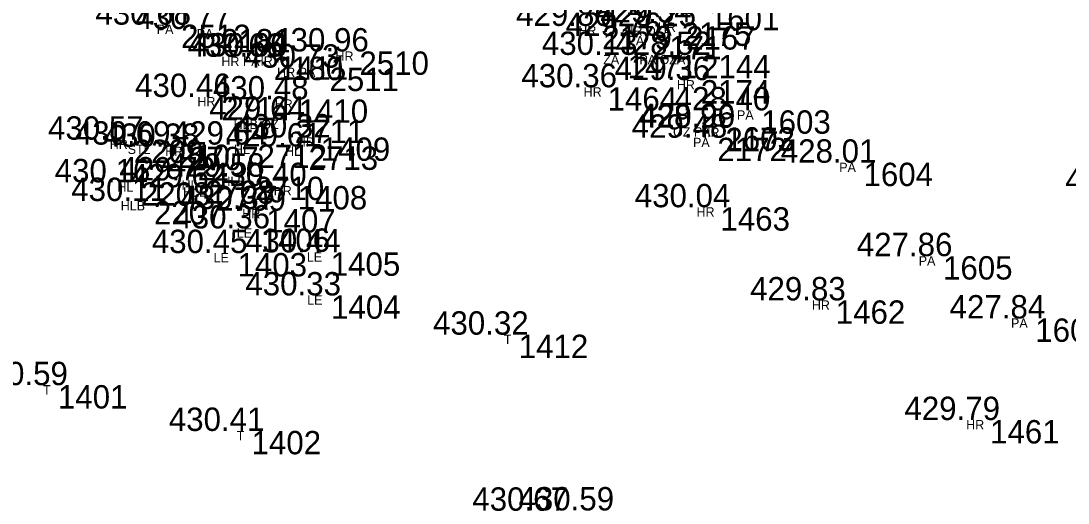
# Model space of a CAD drawing. Extents: x -639390 to -639075, y -1138747 to -1138358.
# Drawn here: x -639296.34 to -639262.75, y -1138603.62 to -1138588.15 of the extents above; entities that cross this region are included whole.
import ezdxf

# ---------------------------------------------------------------- set-up
doc = ezdxf.new("R2010")
doc.units = 0
for name, color, linetype in [('Vrstva 11', 7, 'Continuous'), ('Vrstva 12', 7, 'Continuous'), ('Vrstva 13', 7, 'Continuous'), ('Vrstva 57', 7, 'Continuous')]:
    doc.layers.add(name, color=color, linetype=linetype)

msp = doc.modelspace()

# ---------------------------------------------------------------- linework, layer by layer
at = {"layer": 'Vrstva 11'}
for p, q in [((-639275.42, -1138588.2), (-639275.42, -1138588.2)), ((-639291.48, -1138588.27), (-639291.48, -1138588.27)), ((-639290.2, -1138588.41), (-639290.2, -1138588.41)), ((-639277.97, -1138588.31), (-639277.97, -1138588.31)), ((-639275.28, -1138588.32), (-639275.28, -1138588.32)), ((-639276.38, -1138588.63), (-639276.38, -1138588.63)), ((-639285.76, -1138589.13), (-639285.76, -1138589.13)), ((-639277.16, -1138589.24), (-639277.16, -1138589.24)), ((-639274.8, -1138589.24), (-639274.8, -1138589.24)), ((-639288.51, -1138589.3), (-639288.51, -1138589.3)), ((-639288.35, -1138589.29), (-639288.35, -1138589.29)), ((-639286.72, -1138589.65), (-639286.72, -1138589.65)), ((-639277.8, -1138590.28), (-639277.8, -1138590.28)), ((-639274.81, -1138590.05), (-639274.81, -1138590.05)), ((-639290.19, -1138590.59), (-639290.19, -1138590.59)), ((-639287.71, -1138590.67), (-639287.71, -1138590.67)), ((-639272.87, -1138591.02), (-639272.87, -1138591.02)), ((-639287.83, -1138591.32), (-639287.83, -1138591.32)), ((-639274.02, -1138591.56), (-639274.02, -1138591.56)), ((-639274.02, -1138591.58), (-639274.02, -1138591.58)), ((-639293, -1138591.96), (-639293, -1138591.96)), ((-639287, -1138591.89), (-639287, -1138591.89)), ((-639274.28, -1138591.9), (-639274.28, -1138591.9)), ((-639292.14, -1138592.12), (-639292.14, -1138592.12)), ((-639291.22, -1138592.19), (-639291.22, -1138592.19)), ((-639289.03, -1138592.12), (-639289.03, -1138592.12)), ((-639287.39, -1138592.18), (-639287.39, -1138592.18)), ((-639269.59, -1138592.7), (-639269.59, -1138592.7)), ((-639290.71, -1138593.27), (-639290.71, -1138593.27)), ((-639289.12, -1138593.15), (-639289.12, -1138593.15)), ((-639292.77, -1138593.33), (-639292.77, -1138593.33)), ((-639290.35, -1138593.49), (-639290.35, -1138593.49)), ((-639287.74, -1138593.45), (-639287.74, -1138593.45)), ((-639292.35, -1138593.93), (-639292.35, -1138593.93)), ((-639288.75, -1138594.19), (-639288.75, -1138594.19)), ((-639274.18, -1138594.13), (-639274.18, -1138594.13)), ((-639288.93, -1138594.81), (-639288.93, -1138594.81)), ((-639289.67, -1138595.6), (-639289.67, -1138595.6)), ((-639286.68, -1138595.58), (-639286.68, -1138595.58)), ((-639267.04, -1138595.7), (-639267.04, -1138595.7)), ((-639286.67, -1138596.96), (-639286.67, -1138596.96)), ((-639270.48, -1138597.12), (-639270.48, -1138597.12)), ((-639264.08, -1138597.7), (-639264.08, -1138597.7)), ((-639280.65, -1138598.22), (-639280.65, -1138598.22)), ((-639295.43, -1138599.84), (-639295.43, -1138599.84)), ((-639265.53, -1138600.96), (-639265.53, -1138600.96)), ((-639289.22, -1138601.31), (-639289.22, -1138601.31))]:
    msp.add_line(p, q, dxfattribs=at)

# ---------------------------------------------------------------- texts
at = {"layer": 'Vrstva 12'}
for s, p in [('430.68 ', (-639293.949, -1138588.27)), ('429.86 ', (-639280.456, -1138588.31)), ('429.34 ', (-639277.889, -1138588.2)), ('429.25 ', (-639277.75, -1138588.32)), ('430.77 ', (-639292.669, -1138588.41)), ('429.76 ', (-639278.866, -1138588.63)), ('430.66 ', (-639290.996, -1138589.3)), ('430.90 ', (-639290.849, -1138589.29)), ('430.96 ', (-639288.246, -1138589.13)), ('430.13 ', (-639279.629, -1138589.24)), ('428.52 ', (-639277.269, -1138589.24)), ('430.73 ', (-639289.189, -1138589.65)), ('430.36 ', (-639280.286, -1138590.28)), ('429.36 ', (-639277.296, -1138590.05)), ('430.46 ', (-639292.676, -1138590.59)), ('430.48 ', (-639290.179, -1138590.67)), ('428.40 ', (-639275.369, -1138591.02)), ('429.64 ', (-639290.299, -1138591.32)), ('428.96 ', (-639276.506, -1138591.56)), ('429.29 ', (-639276.489, -1138591.58)), ('430.57 ', (-639295.469, -1138591.96)), ('430.32 ', (-639289.469, -1138591.89)), ('429.48 ', (-639276.749, -1138591.9)), ('430.69 ', (-639294.609, -1138592.12)), ('430.38 ', (-639293.689, -1138592.19)), ('429.64 ', (-639291.499, -1138592.12)), ('429.61 ', (-639289.765, -1138592.18)), ('428.01 ', (-639271.965, -1138592.7)), ('430.16 ', (-639295.256, -1138593.33)), ('429.72 ', (-639293.179, -1138593.27)), ('429.58 ', (-639291.589, -1138593.15)), ('429.62 ', (-639292.819, -1138593.49)), ('430.40 ', (-639290.239, -1138593.45)), ('427.14 ', (-639262.839, -1138593.62)), ('430.11 ', (-639294.725, -1138593.93)), ('430.37 ', (-639291.219, -1138594.19)), ('430.04 ', (-639276.649, -1138594.13)), ('430.36 ', (-639291.416, -1138594.81)), ('430.45 ', (-639292.14, -1138595.6)), ('430.44 ', (-639289.149, -1138595.58)), ('427.86 ', (-639269.526, -1138595.7)), ('430.33 ', (-639289.139, -1138596.96)), ('429.83 ', (-639272.949, -1138597.12)), ('427.84 ', (-639266.549, -1138597.7)), ('430.32 ', (-639283.119, -1138598.22)), ('430.59 ', (-639297.899, -1138599.84)), ('429.79 ', (-639267.999, -1138600.96)), ('430.41 ', (-639291.595, -1138601.31)), ('430.67 ', (-639281.859, -1138603.87)), ('430.59 ', (-639280.379, -1138603.86))]:
    msp.add_text(s, height=0.75, dxfattribs=at).set_placement(p)
at = {"layer": 'Vrstva 13'}
for s, p in [(' 1601', (-639274.52, -1138588.45)), (' 2512', (-639291.48, -1138589.02)), (' 2175', (-639275.42, -1138588.95)), (' 2181', (-639290.2, -1138589.16)), (' 2179', (-639277.97, -1138589.06)), (' 2167', (-639275.28, -1138589.07)), (' 2171', (-639276.38, -1138589.38)), (' 2510', (-639285.76, -1138589.88)), (' 1471', (-639277.16, -1138589.99)), (' 2144', (-639274.8, -1138589.99)), (' 2180', (-639288.51, -1138590.05)), (' 1411', (-639288.35, -1138590.04)), (' 2511', (-639286.72, -1138590.4)), (' 1464', (-639277.8, -1138591.03)), (' 2174', (-639274.81, -1138590.8)), (' 2714', (-639290.19, -1138591.34)), (' 1410', (-639287.71, -1138591.42)), (' 1603', (-639272.87, -1138591.77)), (' 2711', (-639287.83, -1138592.07)), (' 2173', (-639274.02, -1138592.33)), (' 1602', (-639274.02, -1138592.31)), (' 2209', (-639293, -1138592.71)), (' 1409', (-639287, -1138592.64)), (' 2172', (-639274.28, -1138592.65)), (' 2210', (-639292.14, -1138592.87)), (' 2707', (-639291.22, -1138592.94)), (' 2712', (-639289.03, -1138592.87)), (' 2713', (-639287.39, -1138592.93)), (' 1604', (-639269.59, -1138593.45)), (' 2708', (-639290.71, -1138594.02)), (' 2710', (-639289.12, -1138593.9)), (' 2208', (-639292.77, -1138594.08)), (' 2709', (-639290.35, -1138594.24)), (' 1408', (-639287.74, -1138594.2)), (' 2207', (-639292.35, -1138594.68)), (' 1407', (-639288.75, -1138594.94)), (' 1463', (-639274.18, -1138594.88)), (' 1406', (-639288.93, -1138595.56)), (' 1403', (-639289.67, -1138596.35)), (' 1405', (-639286.68, -1138596.33)), (' 1605', (-639267.04, -1138596.45)), (' 1404', (-639286.67, -1138597.71)), (' 1462', (-639270.48, -1138597.87)), (' 1606', (-639264.08, -1138598.45)), (' 1412', (-639280.65, -1138598.97)), (' 1401', (-639295.43, -1138600.59)), (' 1461', (-639265.53, -1138601.71)), (' 1402', (-639289.22, -1138602.06))]:
    msp.add_text(s, height=0.75, dxfattribs=at).set_placement(p)
at = {"layer": 'Vrstva 57'}
for s, p in [('HR', (-639275.909, -1138588.5)), ('PA', (-639291.98, -1138588.57)), ('PA', (-639290.7, -1138588.71)), ('HR', (-639278.459, -1138588.61)), ('HR OZA', (-639276.98, -1138588.62)), ('PA', (-639276.88, -1138588.93)), ('HR', (-639286.249, -1138589.43)), ('ZA', (-639277.66, -1138589.54)), ('PA OZA', (-639276.5, -1138589.54)), ('HR PA', (-639289.91, -1138589.6)), ('HR', (-639288.839, -1138589.59)), ('HR PA', (-639288.12, -1138589.95)), ('HR', (-639278.289, -1138590.58)), ('HR', (-639275.299, -1138590.35)), ('HR', (-639290.679, -1138590.89)), ('HR', (-639288.199, -1138590.97)), ('PA', (-639273.37, -1138591.32)), ('HLB OZ', (-639289.519, -1138591.62)), ('OZ PA', (-639275.42, -1138591.86)), ('HR', (-639274.509, -1138591.88)), ('HR', (-639293.489, -1138592.26)), ('HR', (-639287.489, -1138592.19)), ('PA', (-639274.78, -1138592.2)), ('STL', (-639292.915, -1138592.42)), ('HR', (-639291.709, -1138592.49)), ('HL', (-639289.505, -1138592.42)), ('HL', (-639287.865, -1138592.48)), ('PA', (-639270.09, -1138593)), ('HL', (-639291.185, -1138593.57)), ('HLB', (-639289.909, -1138593.45)), ('HL', (-639293.245, -1138593.63)), ('HLB', (-639291.139, -1138593.79)), ('HR', (-639288.229, -1138593.75)), ('HLB', (-639293.139, -1138594.23)), ('HR', (-639289.239, -1138594.49)), ('HR', (-639274.669, -1138594.43)), ('LE', (-639289.417, -1138595.11)), ('LE', (-639290.157, -1138595.9)), ('LE', (-639287.167, -1138595.88)), ('PA', (-639267.54, -1138596)), ('LE', (-639287.157, -1138597.26)), ('HR', (-639270.969, -1138597.42)), ('PA', (-639264.58, -1138598)), ('T', (-639280.85, -1138598.52)), ('T', (-639295.63, -1138600.14)), ('HR', (-639266.019, -1138601.26)), ('T', (-639289.42, -1138601.61))]:
    msp.add_text(s, height=0.3, dxfattribs=at).set_placement(p)

doc.saveas('drawing.dxf')
